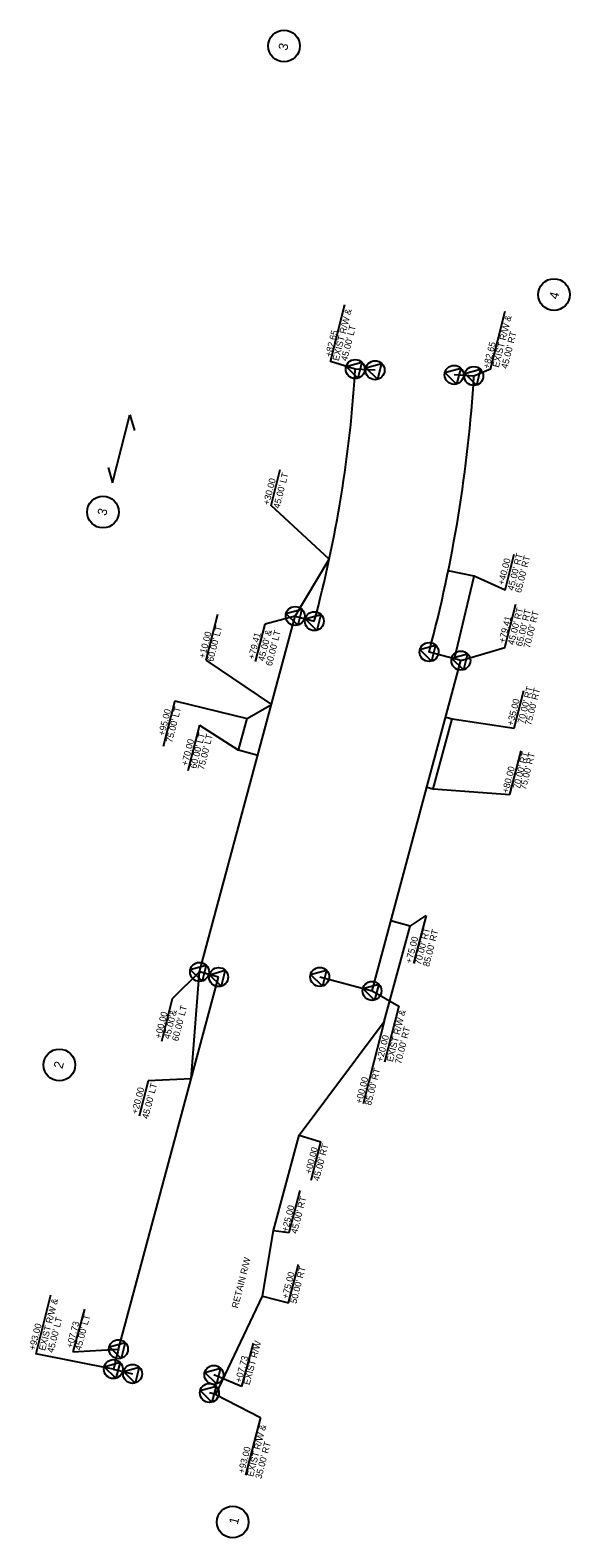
# Model space of a CAD drawing. Extents: x 2079110 to 2079519, y 925933 to 927076.
import ezdxf

# ---------------------------------------------------------------- set-up
doc = ezdxf.new("R2010")
doc.units = 0
for name, color, linetype in [('Prop Easement Construction', 7, 'Continuous'), ('Prop Easement Construction Station Offsets', 7, 'Continuous'), ('Prop Easement Permanent Drainage Station Offsets', 7, 'Continuous'), ('Prop Easement Temporary Drainage', 7, 'Continuous'), ('Prop Easement Temporary Drainage Station Offsets', 7, 'Continuous'), ('Prop Horizontal Alignment Curve and Spiral Data', 7, 'Continuous'), ('Prop Parcel Number CELL', 7, 'Continuous'), ('Prop Parcel Number Text', 7, 'Continuous'), ('Prop ROW Marker CELL', 7, 'Continuous'), ('Prop ROW RW CA Lines', 7, 'Continuous'), ('Prop ROW RW Lines', 7, 'Continuous'), ('Prop ROW Station Offsets', 7, 'Continuous'), ('Prop ROW Text', 7, 'Continuous')]:
    doc.layers.add(name, color=color, linetype=linetype)

msp = doc.modelspace()

# ---------------------------------------------------------------- linework, layer by layer
at = {"layer": 'Prop Easement Construction'}
for p, q in [((2079310.7, 926632.2), (2079336.5, 926675.2)), ((2079446.2, 926662.5), (2079426.6, 926666.5)), ((2079431.4, 926599.7), (2079446.2, 926662.5)), ((2079378.2, 926324.7), (2079397.7, 926397.1)), ((2079397.7, 926397.1), (2079383.2, 926401)), ((2079231.9, 926281.2), (2079238.2, 926362.3)), ((2079313.6, 926238.5), (2079378.2, 926324.7)), ((2079294.2, 926166.1), (2079313.6, 926238.5)), ((2079286, 926116.5), (2079294.2, 926166.1)), ((2079250.6, 926041.8), (2079286, 926116.5)), ((2079250.6, 926041.8), (2079245.7, 926043))]:
    msp.add_line(p, q, dxfattribs=at)
at = {"layer": 'Prop Easement Construction Station Offsets'}
for p, q in [((2079292.5, 926716), (2079299.4, 926743.2)), ((2079336.5, 926675.2), (2079292.5, 926716)), ((2079469.8, 926651.9), (2079476.7, 926679.1)), ((2079469.8, 926651.9), (2079446.2, 926662.5)), ((2079397.7, 926397.1), (2079409.8, 926405.2)), ((2079409.8, 926405.2), (2079400.4, 926368.6)), ((2079378.2, 926324.7), (2079370.4, 926294.1)), ((2079370.4, 926294.1), (2079362.2, 926262.2)), ((2079199.4, 926279.7), (2079192.5, 926252.9)), ((2079231.9, 926281.2), (2079199.4, 926279.7)), ((2079313.6, 926238.5), (2079330.2, 926233.4)), ((2079322.7, 926204.5), (2079330.2, 926233.4)), ((2079306.2, 926164.6), (2079314.4, 926196.5)), ((2079294.2, 926166.1), (2079306.2, 926164.6)), ((2079305.7, 926111.4), (2079313.2, 926140.4)), ((2079286, 926116.5), (2079305.7, 926111.4)), ((2079250.6, 926041.8), (2079284.3, 926024.4)), ((2079284.3, 926024.4), (2079273, 925980.6))]:
    msp.add_line(p, q, dxfattribs=at)
at = {"layer": 'Prop Easement Permanent Drainage Station Offsets'}
msp.add_line((2079322.7, 926204.5), (2079329.6, 926231.1), dxfattribs=at)
at = {"layer": 'Prop Easement Temporary Drainage'}
for p, q in [((2079415.3, 926501.1), (2079429.5, 926554.2)), ((2079424.7, 926555.5), (2079429.5, 926554.2)), ((2079410.4, 926502.4), (2079415.3, 926501.1))]:
    msp.add_line(p, q, dxfattribs=at)
msp.add_lwpolyline([(2079282.3, 926526.5), (2079267.8, 926530.4), (2079274.3, 926554.5), (2079292.7, 926565.1)], dxfattribs=at)
at = {"layer": 'Prop Easement Temporary Drainage Station Offsets'}
for p, q in [((2079251.9, 926633.4), (2079243, 926598.7)), ((2079243, 926598.7), (2079292.7, 926565.1)), ((2079476.7, 926547.2), (2079484, 926575.8)), ((2079219.6, 926568), (2079210.7, 926533.3)), ((2079219.6, 926568), (2079274.3, 926554.5)), ((2079429.5, 926554.2), (2079476.7, 926547.2)), ((2079238.3, 926549.4), (2079229.4, 926514.7)), ((2079238.3, 926549.4), (2079267.8, 926530.4)), ((2079473.2, 926496.9), (2079482, 926529.9)), ((2079415.3, 926501.1), (2079473.2, 926496.9))]:
    msp.add_line(p, q, dxfattribs=at)
at = {"layer": 'Prop Horizontal Alignment Curve and Spiral Data'}
for p, q in [((2079172.3, 926733.2), (2079185.5, 926784.7)), ((2079185.5, 926784.7), (2079188.9, 926773)), ((2079168.9, 926744.8), (2079172.3, 926733.2))]:
    msp.add_line(p, q, dxfattribs=at)
at = {"layer": 'Prop Parcel Number CELL'}
for p, q in [((2079302.3, 927064.5), (2079302.3, 927064.5)), ((2079506.8, 926876), (2079506.8, 926876)), ((2079165, 926711), (2079165, 926711)), ((2079132.1, 926291.8), (2079132.1, 926291.8)), ((2079263.4, 925945.1), (2079263.4, 925945.1))]:
    msp.add_line(p, q, dxfattribs=at)
for centre in [(2079302.3, 927064.5), (2079506.8, 926876), (2079165, 926711), (2079132.1, 926291.8), (2079263.4, 925945.1)]:
    msp.add_circle(centre, 12, dxfattribs=at)
at = {"layer": 'Prop ROW Marker CELL'}
for p, q in [((2079356.2, 926819.5), (2079356.2, 926819.5)), ((2079371.2, 926818.6), (2079371.2, 926818.6)), ((2079431.1, 926815.1), (2079431.1, 926815.1)), ((2079446, 926814.2), (2079446, 926814.2)), ((2079310.7, 926632.2), (2079310.7, 926632.2)), ((2079325.2, 926628.3), (2079325.2, 926628.3)), ((2079412.1, 926604.9), (2079412.1, 926604.9)), ((2079436.2, 926598.4), (2079436.2, 926598.4)), ((2079238.2, 926362.3), (2079238.2, 926362.3)), ((2079252.7, 926358.4), (2079252.7, 926358.4)), ((2079329.3, 926358.5), (2079329.3, 926358.5)), ((2079368.9, 926347.9), (2079368.9, 926347.9)), ((2079176.8, 926076.2), (2079176.8, 926076.2)), ((2079172.9, 926061.1), (2079172.9, 926061.1)), ((2079187.5, 926057.5), (2079187.5, 926057.5)), ((2079249.1, 926056.7), (2079249.1, 926056.7)), ((2079245.7, 926043), (2079245.7, 926043))]:
    msp.add_line(p, q, dxfattribs=at)
for points in [[(2079358.1, 926812.6), (2079349.2, 926821.3), (2079361.2, 926824.7)], [(2079373.1, 926811.7), (2079364.2, 926820.4), (2079376.2, 926823.8)], [(2079433, 926808.1), (2079424.1, 926816.9), (2079436.1, 926820.2)], [(2079448, 926807.3), (2079439.1, 926816), (2079451.1, 926819.4)], [(2079312.6, 926625.2), (2079303.7, 926634), (2079315.7, 926637.3)], [(2079327.1, 926621.3), (2079318.2, 926630.1), (2079330.2, 926633.4)], [(2079414, 926597.9), (2079405.1, 926606.7), (2079417.1, 926610.1)], [(2079438.1, 926591.5), (2079429.2, 926600.2), (2079441.3, 926603.6)], [(2079240.1, 926355.4), (2079231.2, 926364.1), (2079243.2, 926367.5)], [(2079254.6, 926351.5), (2079245.7, 926360.2), (2079257.7, 926363.6)], [(2079331.3, 926351.6), (2079322.4, 926360.3), (2079334.4, 926363.7)], [(2079370.8, 926341), (2079361.9, 926349.7), (2079374, 926353.1)], [(2079178.8, 926069.2), (2079169.9, 926078), (2079181.9, 926081.3)], [(2079174.9, 926054.2), (2079166, 926062.9), (2079178, 926066.3)], [(2079189.4, 926050.5), (2079180.5, 926059.3), (2079192.5, 926062.6)], [(2079251.1, 926049.8), (2079242.2, 926058.5), (2079254.2, 926061.9)], [(2079247.6, 926036), (2079238.7, 926044.8), (2079250.7, 926048.1)]]:
    msp.add_lwpolyline(points, close=True, dxfattribs=at)
for centre in [(2079356.2, 926819.5), (2079371.2, 926818.6), (2079431.1, 926815.1), (2079446, 926814.2), (2079310.7, 926632.2), (2079325.2, 926628.3), (2079412.1, 926604.9), (2079436.2, 926598.4), (2079238.2, 926362.3), (2079252.7, 926358.4), (2079329.3, 926358.5), (2079368.9, 926347.9), (2079176.8, 926076.2), (2079172.9, 926061.1), (2079187.5, 926057.5), (2079249.1, 926056.7), (2079245.7, 926043)]:
    msp.add_circle(centre, 7.2, dxfattribs=at)
at = {"layer": 'Prop ROW RW Lines'}
for p, q in [((2079371.2, 926818.6), (2079356.2, 926819.5)), ((2079446, 926814.2), (2079431.1, 926815.1)), ((2079238.2, 926362.3), (2079310.7, 926632.2)), ((2079310.7, 926632.2), (2079325.2, 926628.3)), ((2079368.9, 926347.9), (2079436.2, 926598.4)), ((2079436.2, 926598.4), (2079412.1, 926604.9)), ((2079176.8, 926076.2), (2079252.7, 926358.4)), ((2079252.7, 926358.4), (2079238.2, 926362.3)), ((2079329.3, 926358.5), (2079368.9, 926347.9)), ((2079172.9, 926061.1), (2079187.5, 926057.5))]:
    msp.add_line(p, q, dxfattribs=at)
for centre, radius, start, end in [((2078399.8, 926876.5), 958.1, 344.9805, 356.5881), ((2078392.6, 926877.7), 1055.4, 345.018, 356.5492), ((2079969.9, 925862.9), 821.2, 164.9465, 166.0316)]:
    msp.add_arc(centre, radius, start, end, dxfattribs=at)
at = {"layer": 'Prop ROW Station Offsets'}
for p, q in [((2079337.5, 926825.2), (2079348.4, 926868.4)), ((2079458.6, 926819.4), (2079469.8, 926863.5)), ((2079356.2, 926819.5), (2079337.5, 926825.2)), ((2079458.6, 926819.4), (2079446, 926814.2)), ((2079469.5, 926608.4), (2079477.8, 926641.1)), ((2079280.7, 926597.7), (2079287.9, 926626.1)), ((2079310.7, 926632.2), (2079287.9, 926626.1)), ((2079436.2, 926598.4), (2079469.5, 926608.4)), ((2079238.2, 926362.3), (2079217.6, 926341.8)), ((2079368.9, 926347.9), (2079389.1, 926336.4)), ((2079217.6, 926341.8), (2079209.4, 926309.6)), ((2079389.1, 926336.4), (2079378.3, 926293.9)), ((2079125.3, 926117.1), (2079114.1, 926072.7)), ((2079151, 926106.5), (2079142.3, 926074.3)), ((2079172.9, 926061.1), (2079114.1, 926072.7)), ((2079278.8, 926080.8), (2079270, 926047.8))]:
    msp.add_line(p, q, dxfattribs=at)
for points in [[(2079142.3, 926074.3), (2079176.8, 926076.2)], [(2079270, 926047.8), (2079249.1, 926056.7)]]:
    msp.add_lwpolyline(points, dxfattribs=at)

# ---------------------------------------------------------------- texts
at = {"layer": 'Prop Easement Construction Station Offsets'}
for s, rotation, p in [('+30.00', 75.7616, (2079291, 926716)), ("45.00' LT", 75.7616, (2079298.8, 926713.4)), ("45.00' RT", 75.7616, (2079476.1, 926651.2)), ('+40.00', 75.7616, (2079468.9, 926655.3)), ("65.00' RT", 75.7616, (2079481.8, 926649.4)), ("70.00' RT", 75.5809, (2079405.8, 926367.2)), ("85.00' RT", 75.5809, (2079412.1, 926365.9)), ('+75.00', 75.5809, (2079398.9, 926368.4)), ("45.00' LT", 75.5809, (2079199.3, 926250.5)), ('+00.00', 75.5809, (2079361.1, 926261.9)), ("85.00' RT", 75.5809, (2079368.1, 926260.7)), ('+20.00', 75.5809, (2079191.3, 926254.1)), ('+00.00', 75.5809, (2079322.8, 926208.7)), ("45.00' RT", 75.5809, (2079328.8, 926203.4)), ("45.00' RT", 75.5809, (2079312.1, 926163.4)), ('+25.00', 75.5809, (2079305.1, 926164.7)), ('+75.00', 75.5809, (2079305.2, 926114.1)), ("50.00' RT", 75.5809, (2079311.6, 926110.4)), ('EXIST R/W &', 75.5809, (2079278.8, 925979.1)), ("35.00' RT", 75.5809, (2079285.1, 925977.5)), ('+93.00', 75.5809, (2079272, 925981.6))]:
    msp.add_text(s, height=5, rotation=rotation, dxfattribs=at).set_placement(p)
at = {"layer": 'Prop Easement Temporary Drainage Station Offsets'}
for s, p in [("60.00' LT", (2079248.6, 926597.2)), ('+10.00', (2079242.3, 926599.7)), ("70.00' RT", (2079483.9, 926550.2)), ("75.00' RT", (2079489.4, 926548.9)), ('+35.00', (2079475.8, 926548.7)), ('+95.00', (2079211.6, 926541)), ("75.00' LT", (2079217.5, 926535.8)), ("60.00' LT", (2079235.7, 926516.1)), ("75.00' LT", (2079241.5, 926515.2)), ('+70.00', (2079229.1, 926518.2)), ("70.00' RT", (2079480.4, 926500.7)), ("75.00' RT", (2079485.4, 926500.1)), ('+80.00', (2079472.1, 926497.5))]:
    msp.add_text(s, height=5, rotation=75.7616, dxfattribs=at).set_placement(p)
at = {"layer": 'Prop Parcel Number Text'}
for s, p in [('3', (2079304.5, 927060.6)), ('4', (2079509.7, 926871.9)), ('3', (2079167.4, 926707.8)), ('2', (2079134.3, 926288.4)), ('1', (2079267.1, 925942.8))]:
    msp.add_text(s, height=7, rotation=75.5812, dxfattribs=at).set_placement(p)
at = {"layer": 'Prop ROW RW CA Lines'}
for s, p in [('EXIST R/W &', (2079121.2, 926074.7)), ('+93.00', (2079113.6, 926075)), ("45.00' LT", (2079127.5, 926073.1))]:
    msp.add_text(s, height=5, rotation=75.7616, dxfattribs=at).set_placement(p)
at = {"layer": 'Prop ROW Station Offsets'}
for s, rotation, p in [('EXIST R/W &', 75.7616, (2079343.7, 926825.3)), ("45.00' LT", 75.7616, (2079350, 926825.2)), ('EXIST R/W &', 75.7616, (2079464.9, 926820.3)), ('+82.65', 75.7616, (2079338, 926828.3)), ('+82.65', 75.7616, (2079457.7, 926819.4)), ("45.00' RT", 75.7616, (2079471.4, 926819.4)), ("45.00' RT", 75.7616, (2079476.4, 926609.9)), ("65.00' RT", 75.7616, (2079482.4, 926608.8)), ("70.00' RT", 75.7616, (2079488.4, 926607.5)), ("60.00' LT", 75.7616, (2079293, 926593.9)), ('+79.41', 75.7616, (2079469.5, 926611.4)), ('+79.41', 75.7616, (2079279.7, 926599)), ("45.00' &", 75.7616, (2079287.2, 926597.5)), ("60.00' LT", 75.5809, (2079222, 926309.4)), ('+00.00', 75.5809, (2079209, 926311.4)), ("45.00'&", 75.5809, (2079215.6, 926311.1)), ('EXIST R/W &', 75.7616, (2079384.6, 926293.7)), ('+20.00', 75.7616, (2079376.8, 926293.7)), ("70.00' RT", 75.7616, (2079390.9, 926292.1)), ('+07.73', 74.9617, (2079142, 926076.6)), ("45.00' LT", 74.9617, (2079148.3, 926074.9)), ('EXIST R/W', 74.9617, (2079276.1, 926048.7)), ('+07.73 ', 74.9617, (2079269.8, 926050.5))]:
    msp.add_text(s, height=5, rotation=rotation, dxfattribs=at).set_placement(p)
at = {"layer": 'Prop ROW Text'}
msp.add_text('RETAIN R/W', height=5, rotation=75.7616, dxfattribs=at).set_placement((2079267.3, 926106.9))

doc.saveas('drawing.dxf')
